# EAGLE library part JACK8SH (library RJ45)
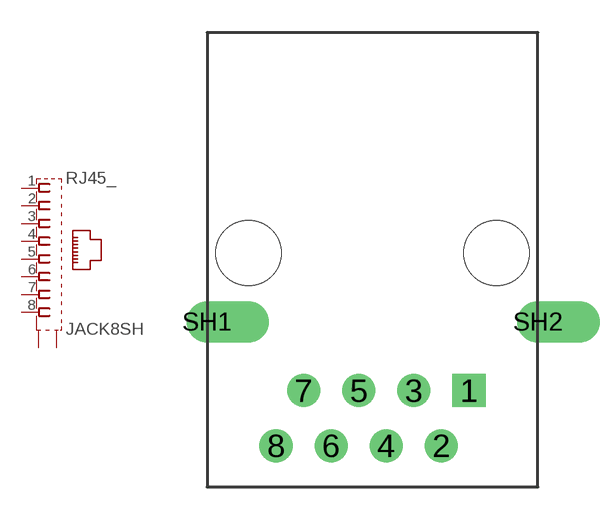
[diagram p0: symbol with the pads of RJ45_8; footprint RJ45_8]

Designator prefix RJ45_

## JACK8SH*  [RJ45_8]
1  1  pas
2  2  pas
3  3  pas
4  4  pas
5  5  pas
6  6  pas
7  7  pas
8  8  pas
SH1  S1  pas
SH2  S2  pas

## Footprint RJ45_8 (pad centres in mm)
drill 1.016 square: 1 4.445,-6.35
drill 1.016 round: 2 3.175,-8.89; 3 1.905,-6.35; 4 0.635,-8.89; 5 -0.635,-6.35; 6 -1.905,-8.89; 7 -3.175,-6.35; 8 -4.445,-8.89
drill 1.27 offset: SH1 -7.62,-3.175; SH2 7.62,-3.175
hole 3 at -5.715,0
hole 3 at 5.715,0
